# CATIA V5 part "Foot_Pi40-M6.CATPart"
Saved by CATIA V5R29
Part number: Foot_Pi40-M6
Description: www.shal.co.kr
Bounding box of the stored display mesh (mm): x -20 to 20, y -20 to 20, z 4 to 62
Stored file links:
  C:\Users\Administrator\Desktop\프로젝트\Boxfold\Foot\Foot_Pi40-M6.CATPart
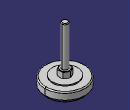
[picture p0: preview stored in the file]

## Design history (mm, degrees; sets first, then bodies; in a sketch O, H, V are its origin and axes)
Body1 (main body)
  Sketch1 on xy-plane, origin (0, 0, 0), H (1, 0, 0), V (0, 1, 0)
    circle A1 centre (0, 0) radius 20
    radius A1 = 20
  Pad1: profile Sketch1, direction (0, 0, 1), length 16, opposite side length -4
  Sketch2 on start face of Pad1, origin (0, 0, 4), H (1, 0, 0), V (0, -1, 0)
    circle A1 centre (0, 0) radius 17.5
    radius A1 = 17.5
  Pocket1: profile Sketch2, direction (0, 0, 1), length 4, outer side
  Sketch3 on end face of Pad1, origin (0, 0, 16), H (1, 0, 0), V (0, 1, 0)
    circle A1 centre (0, 0) radius 12.5
    radius A1 = 12.5
  Pocket2: profile Sketch3, direction (0, 0, -1), length 1, outer side
  Fillet1: radius 1, on edge [face of Pad1 from Sketch1.A1 | end face of Pocket2]
  Fillet2: radius 1, on start face of Pad1
  Sketch4 on end face of Pad1, origin (0, 0, 16), H (1, 0, 0), V (0, 1, 0)
    point P1 (5, 0)
    construction circle A1 centre (0, 0) radius 5.7735
    construction circle A2 centre (0, 0) radius 5
    point P2 (5, -2.8868)
    point P3 (5, 2.8868)
    point P4 (0, 5.7735)
    point P5 (-5, 2.8868)
    point P6 (-5, -2.8868)
    point P7 (0, -5.7735)
    line L1 (5, -2.8868) -> (5, 2.8868)
    line L2 (5, 2.8868) -> (0, 5.7735)
    line L3 (0, 5.7735) -> (-5, 2.8868)
    line L4 (-5, 2.8868) -> (-5, -2.8868)
    line L5 (-5, -2.8868) -> (0, -5.7735)
    line L6 (0, -5.7735) -> (5, -2.8868)
    construction line L7 (0, 0) -> (5, 0)
    radius A2 = 5
    coincidence: A1 P2, A1 P3, A1 P4, A1 P5, A1 P6, A1 P7
    tangency: A2 L1, A2 L2, A2 L3, A2 L4, A2 L5, A2 L6
    midpoint: P1 L1
    horizontal: L7 H
  Pad2: profile Sketch4, direction (0, 0, 1), length 6
  Sketch5 on yz-plane, origin (0, 0, 0), H (0, 1, 0), V (0, 0, 1)
    point P1 (4.9, 16)
    line L1 (4.9, 16) -> (5.7735, 16)
    point P2 (5.7735, 16)
    line L2 (5.7735, 16) -> (5.7735, 16.5043)
    line L3 (5.7735, 16.5043) -> (4.9, 16)
    reference projected line E1 through (0, 0) direction (0, 1) from axis of face of Pad1 from Sketch1.A1
    reference projected line E2 (5.7735, 16) -> (5.7735, 22) from edge [face of Pad2 from Sketch4.L3 | face of Pad2 from Sketch4.L2]
    reference intersected line E3 (-20, 16) -> (20, 16) from end face of Pad1
    reference projected line E4 (2.8868, 16) -> (5.7735, 16) from edge [end face of Pad1 | face of Pad2 from Sketch4.L2]
    distance P1 E1 = 4.9
    angle E4 L3 = 30
    horizontal: L1 H
    vertical: L2 V
    coincidence: P2 E2, L1 E3
  Groove1: profile Sketch5, axis Z axis, angle 360
  Sketch6 on end face of Pad2, origin (0, 0, 22), H (1, 0, 0), V (0, 1, 0)
    circle A1 centre (0, 0) radius 4.5
    radius A1 = 4.5
  Pocket3: profile Sketch6, direction (0, 0, -1), length 0.4, outer side
  Sketch7 on end face of Pad2, origin (0, 0, 22), H (1, 0, 0), V (0, 1, 0)
    circle A1 centre (0, 0) radius 3
    radius A1 = 3
  Pad3: profile Sketch7, direction (0, 0, 1), length 40
  Thread1: "M6", diameter 6, depth 40, pitch 1, on face of Pad3 from Sketch7.A1, from end face of Pad3
  Chamfer1: length 0.6, angle 45, on end face of Pad3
